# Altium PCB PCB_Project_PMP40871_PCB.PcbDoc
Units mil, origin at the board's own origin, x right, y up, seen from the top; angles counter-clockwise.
Board outline 2300 x 1200 mil, 2 copper layers (Top Layer, Bottom Layer), stack 35.6 mil thick; 25 components, 9 nets, 72 pads, 26 vias.
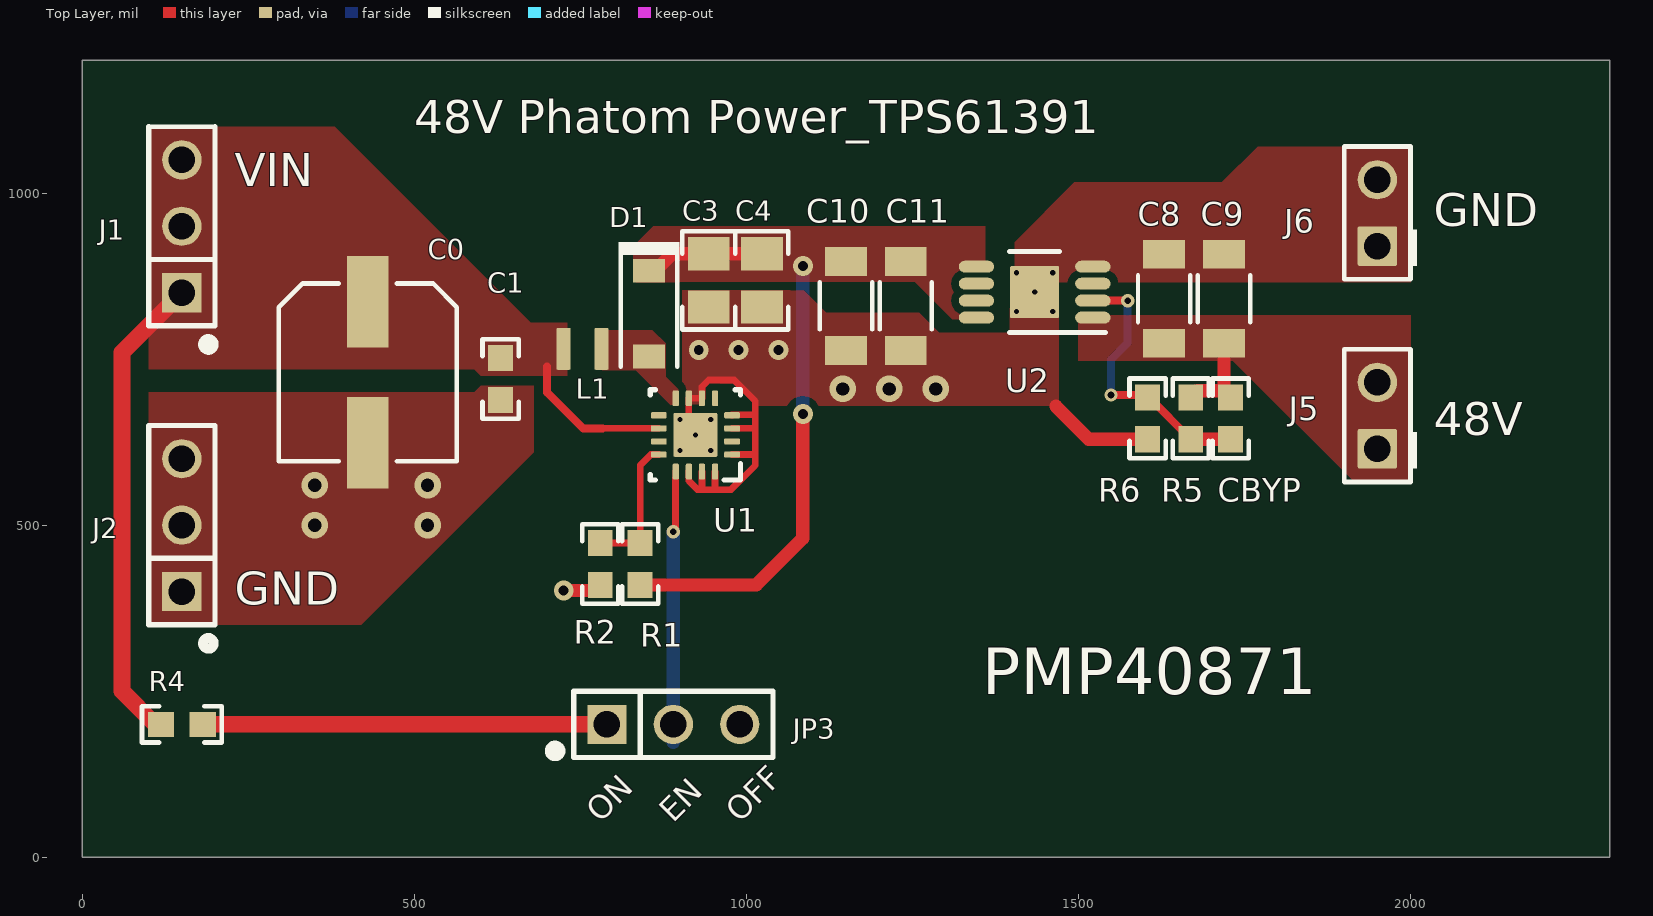
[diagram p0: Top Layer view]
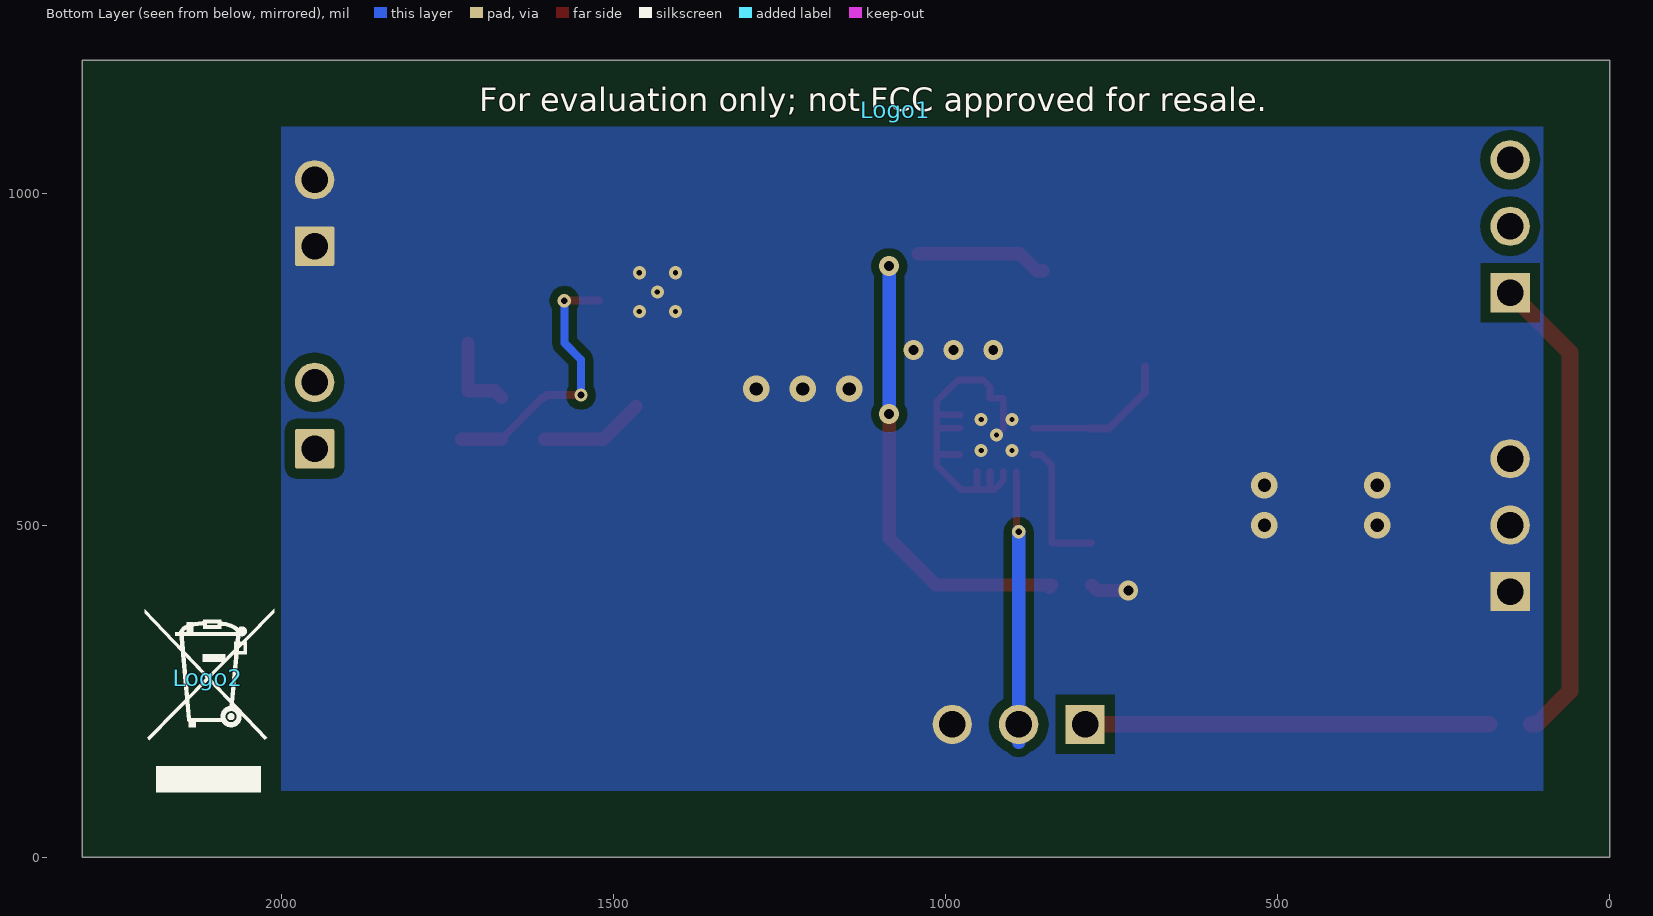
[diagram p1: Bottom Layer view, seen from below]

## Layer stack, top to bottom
Top Solder: solder mask 0.4, Solder Resist, Dk 3.5
Top Layer: signal copper 2.8
Dielectric1: core 30, Dk 4.2
Bottom Layer: signal copper 2.8
Bottom Solder: solder mask 0.4, Solder Resist, Dk 3.5

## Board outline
0,0 2300,0 2300,1200 0,1200

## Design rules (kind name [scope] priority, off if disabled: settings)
AcuteAngle [All] p1: minimum=4.50000000000000E+0001 checktracksonly=FALSE
AssemblyTestPointUsage [All] p1: valid=2
Clearance Clearance_BoardEdge_MountingHoles [OnCopper and InComponentClass('Mounting Holes') vs IsKeepOut] p1: gap=40 ignorepadtopadclearanceinfootprint=FALSE except(0: Arc-Hole Track-Hole SMDPad-Hole THPad-Hole Via-Hole Fill-Hole Poly-Hole Region-Hole Text-Hole)
Clearance Clearance_BoardEdge_Poly [OnCopper and InPoly vs IsKeepOut] p2: gap=25 ignorepadtopadclearanceinfootprint=FALSE except(0: Arc-Hole Track-Hole SMDPad-Hole THPad-Hole Via-Hole Fill-Hole Poly-Hole Region-Hole Text-Hole)
Clearance Clearance_BoardEdge [OnCopper and Not InComponentClass('Logo') and not InComponentClass('FiducialMark') and not InRegion(1000,500,4000,800) and Not IsKeepout vs IsKeepOut] p3: gap=5 ignorepadtopadclearanceinfootprint=FALSE except(0: Arc-Hole Track-Hole SMDPad-Hole THPad-Hole Via-Hole Fill-Hole Poly-Hole Region-Hole Text-Hole)
Clearance Clearance_Poly [InPolygon] p4: gap=10 ignorepadtopadclearanceinfootprint=FALSE except(0: Arc-Hole Track-Hole SMDPad-Hole THPad-Hole Via-Hole Fill-Hole Poly-Hole Region-Hole Text-Hole)
Clearance [All] p5: gap=7.5 ignorepadtopadclearanceinfootprint=FALSE
ComponentClearance ComponentClearance_Logo [All] p1: gap=10 collisioncheckmode=3 verticalgap=10 showdistances=TRUE
ComponentClearance ComponentClearance_ScrewToNut [(HasFootprint('NY PMS 440 0025 PH')) vs (HasFootprint('Keystone_1902C'))] p2: gap=5 collisioncheckmode=3 verticalgap=10 showdistances=FALSE
ComponentClearance ComponentClearance_MountingHoles [InComponentClass('Mounting Holes')] p3: gap=10 collisioncheckmode=3 verticalgap=100000 showdistances=FALSE
ComponentClearance ComponentClearance_SmallPassives [HasFootprint('0201*') or HasFootprint('0402*') or HasFootprint('0508') or HasFootprint('0603*') or HasFootprint('0612') or HasFootprint('0805*') or HasFootprint('0815*') or HasFootprint('0830*') or HasFootprint('1206*') or HasFootprint('1210*') or HasFootprint('1808*') or HasFootprint('1812*') or HasFootprint('1825*') or HasFootprint('2010*') or HasFootprint('2220*') or HasFootprint('2225*') or HasFootprint('2512*') or HasFootprint('2728*') or HasFootprint('3518*') vs HasFootprint('0201*') or HasFootprint('0402*') or HasFootprint('0508') or HasFootprint('0603*') or HasFootprint('0612') or HasFootprint('0805*') or HasFootprint('0815*') or HasFootprint('0830*') or HasFootprint('1206*') or HasFootprint('1210*') or HasFootprint('1808*') or HasFootprint('1812*') or HasFootprint('1825*') or HasFootprint('2010*') or HasFootprint('2220*') or HasFootprint('2225*') or HasFootprint('2512*') or HasFootprint('2728*') or HasFootprint('3518*')] p4: gap=10 collisioncheckmode=3 verticalgap=10 showdistances=FALSE
ComponentClearance ComponentClearance_THtoSMT [IsThruComponent vs IsSMTComponent] p5: gap=10 collisioncheckmode=3 verticalgap=100000 showdistances=FALSE
ComponentClearance ComponentClearance_THtoTH [IsThruComponent vs IsThruComponent] p6: gap=10 collisioncheckmode=3 verticalgap=100000 showdistances=FALSE
ComponentClearance [All] p7: gap=10 collisioncheckmode=3 verticalgap=10 showdistances=FALSE
DiffPairsRouting [All] p1: maxlimit=100 minlimit=10 mostfreqgap=10 toplayer_minwidth=15 toplayer_maxwidth=15 toplayer_prefwidth=15 bottomlayer_minwidth=15 bottomlayer_maxwidth=15 bottomlayer_prefwidth=15 maxuncoupledlength=1000
FabricationTestPointUsage TestPointUsage [All] p1: valid=2 allowmultiple=FALSE
FabricationTestpoint Testpoint [All] p1: side=3 testpointundercomponent=TRUE minsize=40 maxsize=100 preferedsize=60 minholesize=0 maxholesize=40 preferedholesize=32 testpointgrid=1 allowsidetop=TRUE allowsidebottom=TRUE usegrid=TRUE gridtolerance=0.01
FanoutControl Fanout_LCC [IsLCC] p1: bgadir=Out bgaviamode=Centered fanoutstyle=Auto fanoutdirection=Alternating viagrid=1 // Fanout_LCC (Default Rule)
FanoutControl Fanout_BGA [IsBGA] p2: bgadir=Out bgaviamode=Centered fanoutstyle=Auto fanoutdirection=Alternating viagrid=1 // Fanout_BGA (Default Rule)
FanoutControl Fanout_Default [All] p4: bgadir=Out bgaviamode=Centered fanoutstyle=Auto fanoutdirection=Alternating viagrid=1 // Fanout_Default (Default Rule)
FanoutControl Fanout_Small [(CompPinCount < 5)] p5: bgadir=Out bgaviamode=Centered fanoutstyle=Auto fanoutdirection=OutThenIn viagrid=1 // Fanout_Small (Default Rule)
HoleSize [All] p1: absolutevalues=TRUE maxlimit=251 minlimit=6 maxpercent=80.000 minpercent=20.000
MinimumAnnularRing [All] p1: minimumring=3
MinimumSolderMaskSliver MinimumSolderMaskSliver_Logo [InComponentClass('Logo') vs InComponentClass('Logo')] p1: minsoldermaskwidth=0.7
MinimumSolderMaskSliver [All] p2: minsoldermaskwidth=0
PlaneConnect [All] p1: planeconnectstyle=Direct reliefexpansion=10 reliefentries=4 reliefconductorwidth=10 reliefairgap=10
PolygonConnect [All] p1: connectstyle=Direct reliefconductorwidth=10 reliefentries=4 polygonreliefangle="90 Angle" airgapwidth=10
RoutingCorners [All] p1: cornerstyle=45-Degree minsetback=10 maxsetback=100
RoutingVias [All] p1: holewidth=16 width=34 viastyle="Through Hole" minholewidth=7 minwidth=16 maxholewidth=40 maxwidth=65
SMDToCorner [All] p1: distance=0
SilkToBoardRegionClearance [Not ((IsComment or IsDesignator) And (Hide <> 'False')) and not InRegion(1000,500,4000,800)] p1:
SilkToSilkClearance [All] p1: silktosilkclearance=0
SilkToSolderMaskClearance SilkscreenOverComponentPads [IsPad] p1: minsilkscreentomaskgap=0 clearancetoexposedcopper=TRUE
SolderMaskExpansion [All] p1: expansion=3
Width [All] p1: maxlimit=100 minlimit=6 preferedwidth=10 checkconnectedcopper=TRUE
14 further rules are at their usual default settings.

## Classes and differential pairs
component class Header: J1 J2 J5 J6 J7 J9 JP3

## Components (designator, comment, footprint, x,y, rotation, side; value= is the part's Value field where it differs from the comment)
C0 "EEHZA1E101XP" SM_RADIAL_6.3BMM 430,730 r270 top value=100uF
C1 "GRM188R61C475KAAJ" 0603 630,720 r270 top value=4.7uF
C3 "C2012X7S2A474K125AB" 0805_HV 943.29,868.52 r270 top value=0.47uF
C4 "C2012X7S2A474K125AB" 0805_HV 1023.29,868.52 r270 top value=0.47uF
C8 "CGA5L1X7R1H106K160AC" 1206_190 1629.02,840.87 r90 top value=10uF
C9 "CGA5L1X7R1H106K160AC" 1206_190 1719.02,840.87 r90 top value=10uF
C10 "CGA5L3X7S2A225K160AB" 1206_180 1150,830 r270 top value=2.2uF
C11 "CGA5L3X7S2A225K160AB" 1206_180 1240,830 r270 top value=2.2uF
CBYP "C0603C103J1RACTU" 0603 1729.02,660.87 r270 top value=0.01uF
D1 "BAS16D-E3-08" SOD-123 853.29,818.52 r270 top value=100V
J1 "Header_3x1_Launchpad" CONN_PEC03SAAN 150,950 r90 top
J2 "Header_3x1_Launchpad" CONN_PEC03SAAN 150,500 r90 top
J5 "Header_2x1" CONN_PEC02SAAN 1950,665 r90 top
J6 "Header_2x1" CONN_PEC02SAAN 1950,970 r90 top
JP3 "Header_3x1_Launchpad" CONN_PEC03SAAN 890,200 r0 top
L1 "DFE201612E-4R7M=P2" DFE201612E 753.29,765.41 r0 top value=4.7uH
Logo1 "FCC disclaimer" FCC_disclaimer 1075,1125 r180 bottom
Logo2 "WEEE logo" WEEE_Minimum 2110,270 r180 bottom
R1 "RT0603BRD07392KL" 0603 840,441.5 r270 top value=392k
R2 "Resistor" 0603 780,441.5 r90 top value=10.0k
R4 "Resistor" 0603 150,200 r180 top value=10.0k
R5 "RC0603FR-07475KL" 0603 1669.02,660.87 r90 top value=475k
R6 "RC0603FR-0712KL" 0603 1604.02,660.87 r90 top value=12.0k
U1 "TPS61391RGT" RGT0016C 923.29,635.78 r180 top
U2 "TPS7A4101DGNR" DGN0008B_N 1434.02,850.87 r180 top

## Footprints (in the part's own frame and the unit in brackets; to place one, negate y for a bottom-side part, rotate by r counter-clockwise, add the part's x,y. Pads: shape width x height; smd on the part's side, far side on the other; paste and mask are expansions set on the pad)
0603 [mm] "0603 from SM-752 data"
  rect 1x0.95 smd: 1(-0.8,0) 2(0.8,0)
  silkscreen extent -1.52,-0.69 1.52,0.69, body extent -0.87,-0.47 0.87,0.47, height 1
0805_HV [mil] "0805 with 30mil clearance between pads"
  rect 50x63 smd: 1(-40,0) 2(40,0)
  silkscreen extent -74,-40 74,40, body extent -43,-29 43,29, height 57
1206_180 [mm] "1206_180"
  rect 1.1x1.6 smd: 1(-1.7,0) 2(1.7,0)
  silkscreen extent -0.9,-1 0.9,1, body extent -1.75,-0.95 1.75,0.95, height 1.8
1206_190 [mm] "1206_190"
  rect 1.1x1.6 smd: 1(-1.7,0) 2(1.7,0)
  silkscreen extent -0.9,-1 0.9,1, body extent -1.75,-0.95 1.75,0.95, height 1.9
CONN_PEC02SAAN [mm] "SULLINS"
  rrect7% 1.5x1.5 hole 1.016: 1(-1.27,0)
  round 1.5 hole 1.016: 2(1.27,0)
  silkscreen extent -2.54,-1.52 2.54,1.27, body extent -2.54,-1.27 2.54,1.27, height 8.38
CONN_PEC03SAAN [mm] "SULLINS"
  rect 1.5x1.5 hole 1.016: 1(-2.54,0)
  round 1.5 hole 1.016: 2(0,0) 3(2.54,0)
  silkscreen extent -4.72,-1.27 3.81,1.27, body extent -3.84,-1.3 3.84,1.3, height 8.38
DFE201612E [mm] "MuRata recommended"
  rrect18% 0.55x1.6 smd: 1(-0.725,0) 2(0.725,0)
  body extent -1.1,-0.9 1.1,0.9, height 1.2
DGN0008B_N [mm] "TSOP, 8-Leads, Body 3x3mm, Pitch 0.65mm, Thermal Pad 1.92x1.60mm, IPC Medium Density"
  rrect100% 1.35x0.45 smd: 1(-2.225,0.975) 2(-2.225,0.325) 3(-2.225,-0.325) 4(-2.225,-0.975) 5(2.225,-0.975) 6(2.225,-0.325) 7(2.225,0.325) 8(2.225,0.975)
  rrect5% 1.88x1.98 smd: 9(0,0)
  silkscreen extent -2.7,-1.55 0.95,1.55, body extent -2.46,-1.5 2.46,1.5, height 1.1
FCC_disclaimer [mil]
RGT0016C [mm] "QFN, 16-Leads, Body 3x3mm, Pitch 0.5mm, Thermal Pad 1.7x1.7mm, TI Recommended"
  rrect42% 0.6x0.24 smd: 1(-1.4,0.75) 2(-1.4,0.25) 3(-1.4,-0.25) 4(-1.4,-0.75) 9(1.4,-0.75) 10(1.4,-0.25) 11(1.4,0.25) 12(1.4,0.75)
  rrect42% 0.24x0.6 smd: 5(-0.75,-1.4) 6(-0.25,-1.4) 7(0.25,-1.4) 8(0.75,-1.4) 13(0.75,1.4) 14(0.25,1.4) 15(-0.25,1.4) 16(-0.75,1.4)
  rrect6% 1.55x1.55 on Top Paste: 17(0,0)
  rrect6% 1.68x1.68 smd paste-0.85: 17(0,0)
  silkscreen extent -1.72,-1.72 1.73,1.73, body extent -1.5,-1.5 1.5,1.5, height 1
SM_RADIAL_6.3BMM [mm] "Nichicon 6.3x7.7"
  rect 3.5x1.6 smd: 1(-2.7,0) 2(2.7,0)
  silkscreen extent -3.4,-3.4 3.4,3.4, body extent -3.4,-3.4 3.4,3.4, height 8
SOD-123 [mm] "On Semi recommended land pattern"
  rect 0.915x1.22 smd: 1(-1.637,0) 2(1.637,0)
  silkscreen extent -2.74,-1.17 2.03,1.17, body extent -1.93,-0.9 1.93,0.9, height 1.35
WEEE_Minimum [mil] "WEEElie bin"
  silkscreen extent -95,-172 99,104

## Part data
C0: library part CMP-0012570-3, "CAP, Polymer Hybrid, 100 uF, 25 V, +/- 20%, 30 ohm, 6.3x7.7 SMD", Manufacturer=Panasonic, Supplier Part Number 1=P15436CT-ND, Tolerance_%=20%, Value1="30 ohm", Value2=25V, ValueDisplayed=100uF
C1: library part CMP-0007341-5, "CAP, CERM, 4.7 uF, 16 V, +/- 10%, X5R, 0603", Cap_Case=0603, Manufacturer=MuRata, Supplier Part Number 1=490-10481-1-ND, TempCo=X5R, Tolerance_%=10%, Value1=Unknown, Value2=16V, ValueDisplayed=4.7uF
C3 C4: "CAP, CERM, 0.47 µF, 100 V,+/- 10%, X7S, 0805", Cap_Case=0805, Manufacturer=TDK, Supplier Part Number 1=445-5203-1-ND, TempCo=X7S, Tolerance_%=10, Value1="0.017152 ohm", Value2=100V, ValueDisplayed=0.47µF
C8 C9: library part CMP-0085950-1, "CAP, CERM, 10 µF, 50 V,+/- 10%, X7R, AEC-Q200 Grade 1, 1206", Cap_Case=1206, Manufacturer=TDK, TempCo=X7R, Tolerance_%=10%, Value2=50V, ValueDisplayed=10µF
C10 C11: "CAP, CERM, 2.2 µF, 100 V,+/- 10%, X7S, AEC-Q200 Grade 1, 1206", Cap_Case=1206, Manufacturer=TDK, Supplier Part Number 1=445-6994-1-ND, TempCo=X7S, Tolerance_%=10, Value1="0.005718 ohm", Value2=100V, ValueDisplayed=2.2µF
CBYP: "CAP, CERM, 0.01 µF, 100 V,+/- 5%, X7R, 0603", Cap_Case=0603, Manufacturer=Kemet, Supplier Part Number 1=399-3190-1-ND, TempCo=X7R, Tolerance_%=5, Value2=100V, ValueDisplayed=0.01µF
D1: library part CMP-0080761-1, "Diode, Switching, 100 V, 0.25 A, AEC-Q101, SOD-123", Manufacturer=Vishay-Semiconductor, Supplier Part Number 1=BAS16D-E3-08GICT-ND, Value1=0.25A, Value2=1.25V
J1 J2 JP3: library part CMP-0002338-1, "Header, 100mil, 3x1, Tin, TH", Color=Black, Current_A=3A, Manufacturer="Sullins Connector Solutions", PartNumber=PEC03SAAN, Supplier Part Number 1=S1012E-03-ND, Voltage_V=1.8kV
J5 J6: library part CMP-0002337-1, "Header, 100mil, 2x1, Tin, TH", Color=Black, Current_A=3A, Manufacturer="Sullins Connector Solutions", PartNumber=PEC02SAAN, Supplier Part Number 1=S1012E-02-ND, Voltage_V=1.8kV
L1: library part CMP-0080776-1, "Inductor, Shielded, Metal Composite, 4.7 µH, 1.2 A, 0.252 ohm, SMD", Manufacturer=MuRata, PartNumber=DFE201612E-4R7M{}P2, Value1="0.252 ohm", Value2=1.2A, ValueDisplayed=4.7µH
Logo1: library part CMP-0074847-1, "FCC_disclaimer"
Logo2: library part CMP-0074769-1
R1: "RES, 392 k, 0.1%, 0.1 W, 0603", Manufacturer="Yageo America", Power_W=0.1, TempCo="25 ppm/C", Value1=0.1%, Value2=0.1W, Value_Code=392k
R2 R4: library part CMP-0021998-4, "RES, 10.0 k, 1%, 0.1 W, AEC-Q200 Grade 0, 0603", Manufacturer=Vishay-Dale, PartNumber=CRCW060310K0FKEA, Power_W=100mW, Supplier Part Number 1=541-10.0KHCT-ND, TempCo="100 ppm/C", Tolerance_%=1%, Value2=0.1W, Value_Code=10k0, ValueDisplayed=10.0k
R5: library part CMP-0023130-4, "RES, 475 k, 1%, 0.1 W, 0603", Manufacturer=Yageo, Power_W=100mW, Supplier Part Number 1=311-475KHRCT-ND, TempCo="100 ppm/C", Tolerance_%=1%, Value2=0.1W, Value_Code=475k
R6: library part CMP-0022779-5, "RES, 12.0 k, 1%, 0.1 W, 0603", Manufacturer=Yageo, Power_W=100mW, Supplier Part Number 1=311-12.0KHRCT-ND, TempCo="100 ppm/C", Tolerance_%=1%, Value2=0.1W, Value_Code=12k0, ValueDisplayed=12.0k
U1: library part CMP-0860736-1, "85-VOUT Boost Converter with Current Mirror and Sample / Hold, RGT0016C (VQFN-16)", Alternate Manufacturer="Texas Instruments"
U2: "Single Output LDO, 50 mA, Adjustable 1.175 to 48 V Output, 7 to 50 V Input, 8-pin MSOP (DGN), -40 to 125 degC, Green (RoHS & no Sb/Br)", Alternate Manufacturer="Texas Instruments", Alternate PartNumber=Equivalent, Supplier Part Number 1=296-30081-2-ND

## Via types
v1: diameter 19.68, hole 7.87, Top Layer to Bottom Layer, 10 vias
v2: diameter 40, hole 20, Top Layer to Bottom Layer, 7 vias
v3: diameter 30, hole 15, Top Layer to Bottom Layer, 6 vias
v4: diameter 20, hole 10, Top Layer to Bottom Layer, 3 vias

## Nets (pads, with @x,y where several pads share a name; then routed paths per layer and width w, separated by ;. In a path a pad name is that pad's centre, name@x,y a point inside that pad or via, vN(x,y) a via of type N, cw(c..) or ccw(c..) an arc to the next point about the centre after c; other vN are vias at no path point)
EN: JP3.2 U1.13 | length 409.4
  Top Layer w10: v4(890,490) 893.29,493.29 893.29,570.78 893.76,571.25 U1.13
  Bottom Layer w20: JP3.2@890,172.79 v4(890,490)
FB: R1.1 R2.2 U1.12 | length 211.9
  Top Layer w10: R2.2 R1.1 840,590 856.25,606.25 U1.12
FB1: CBYP.2 R5.1 R6.2 U2.2 | length 405.1
  Top Layer w12: U2.2 v4@1566.81,838.07 ; v4(1549.02,695.87) 1600.51,695.87 R6.2 1606.02,692.36 R5.1
  Top Layer w20: R5.1 CBYP.2
  Bottom Layer w12: v4(1549.02,695.87) 1549.02,749.02 1574.02,774.02 v4(1574.02,837.87)
GND: C0.2 C1.2 C3.2 C4.2 C8.2 C9.2 C10.2 C11.2 J2.1 J2.2 J2.3 J6.1 J6.2 JP3.3 R2.1 R6.1 U1.1 U1.3 U1.4 U1.6 U1.7 U1.14 U1.15 U1.16 U1.17@923.29,635.78 U2.4 U2.9 | length 797.9
  Top Layer w10: U1.14 913.44,566.56 926.48,553.52 976.85,553.52 1013.29,589.95 1013.29,686.71 981.48,718.52 943.29,718.52 933.13,708.36 U1.6 U1.7 913.44,645.62 v1(923.29,635.78) ; 933.13,553.67 U1.15 ; 952.81,553.99 U1.16 ; U1.1 1009.74,606.25 1010,606.52 ; U1.3 1013.29,645.62 ; U1.4 978.4,666 1013.29,666
  Top Layer w20: v3(725,401.5) 771.5,401.5 R2.1 ; 1466.07,678.93 1515.63,629.37 R6.1
  other v1: 900.06,612.55 946.52,612.55 900.06,659.01 946.52,659.01 1406.85,821.73 1461.18,821.73 1434.02,850.87 1406.85,880 1461.18,880
  other v2: 350,500 520,500 350,560 520,560 1145,705 1215,705 1285,705
  other v3: 928.29,763.52 988.29,763.52 1048.29,763.52
NetJP3_1: JP3.1 R4.1 | length 608.5
  Top Layer w25: R4.1 JP3.1
SW: D1.2 L1.2 U1.8
VIN: C0.1 C1.1 J1.1 J1.2 J1.3 L1.1 R4.2 U1.10 | length 945.7
  Top Layer w10: 783.29,645.62 U1.10
  Top Layer w12: 700,738.52 700,700 754.38,645.62 783.29,645.62
  Top Layer w25: R4.2 110,200 60,250 60,760 J1.1
VOUT: C8.1 C9.1 CBYP.1 J5.1 J5.2 R5.2 U2.1 | length 125.7
  Top Layer w20: R5.2 1679.02,702.36 1719.02,702.36 C9.1
Vout1: C3.1 C4.1 C10.1 C11.1 D1.1 R1.2 U2.5 U2.8 | length 887.7
  Top Layer w20: R1.2@843.5,406.5 R1.2 1015,410 1085,480 v3(1085,667.23) ; D1.1 862.98,882.98 888.52,908.52 C3.1 C4.1 C4.1@1041.48,908.52
  Bottom Layer w20: v3(1085,667.23) v3(1085,890)
pads on no net: U1.2 U1.5 U1.9 U1.11 U1.17@923.29,635.78 U2.3 U2.6 U2.7
copper on no net: | length 60632.3
  Top Layer w1: 6346.64,537.82 6446.33,637.5 6566.33,757.5 6686.33,877.5 6806.33,997.5 6926.33,1117.5 7046.33,1237.5 ; 6346.64,597.82 6386.33,637.5 6506.33,757.5 6626.33,877.5 6746.33,997.5 6866.33,1117.5 6986.33,1237.5 ; 6346.64,657.82 6446.33,757.5 6566.33,877.5 6686.33,997.5 6806.33,1117.5 6926.33,1237.5 ; 6346.64,717.82 6386.33,757.5 6506.33,877.5 6626.33,997.5 6746.33,1117.5 6866.33,1237.5 ; 6346.64,777.82 6446.33,877.5 6566.33,997.5 6686.33,1117.5 6806.33,1237.5 ; 6346.64,837.82 6386.33,877.5 6506.33,997.5 6626.33,1117.5 6746.33,1237.5 ; 6346.64,897.82 6446.33,997.5 6566.33,1117.5 6686.33,1237.5 ; 6346.64,957.82 6386.33,997.5 6506.33,1117.5 6626.33,1237.5 ; 6346.64,1017.82 6446.33,1117.5 6566.33,1237.5 ; 6346.64,1077.82 6386.33,1117.5 6506.33,1237.5 ; 6346.64,1137.82 6446.33,1237.5 ; 6346.64,1197.82 6386.33,1237.5 ; 6386.33,517.5 6506.33,637.5 6626.33,757.5 6746.33,877.5 6866.33,997.5 6986.33,1117.5 7106.33,1237.5 ; 6446.33,517.5 6566.33,637.5 6686.33,757.5 6806.33,877.5 6926.33,997.5 7046.33,1117.5 7166.33,1237.5 ; 6506.33,517.5 6626.33,637.5 6746.33,757.5 6866.33,877.5 6986.33,997.5 7106.33,1117.5 7226.33,1237.5 ; 6566.33,517.5 6686.33,637.5 6806.33,757.5 6926.33,877.5 7046.33,997.5 7166.33,1117.5 7286.33,1237.5 ; 6626.33,517.5 6746.33,637.5 6866.33,757.5 6986.33,877.5 7106.33,997.5 7226.33,1117.5 7346.33,1237.5 ; 6686.33,517.5 6806.33,637.5 6926.33,757.5 7046.33,877.5 7166.33,997.5 7286.33,1117.5 7406.33,1237.5 ; 6746.33,517.5 6866.33,637.5 6986.33,757.5 7106.33,877.5 7226.33,997.5 7346.33,1117.5 7466.33,1237.5 ; 6806.33,517.5 6926.33,637.5 7046.33,757.5 7166.33,877.5 7286.33,997.5 7406.33,1117.5 7466.33,1177.5 ; 6866.33,517.5 6986.33,637.5 7106.33,757.5 7226.33,877.5 7346.33,997.5 7466.33,1117.5 ; 6926.33,517.5 7046.33,637.5 7166.33,757.5 7286.33,877.5 7406.33,997.5 7466.33,1057.5 ; 6986.33,517.5 7106.33,637.5 7226.33,757.5 7346.33,877.5 7466.33,997.5 ; 7046.33,517.5 7166.33,637.5 7286.33,757.5 7406.33,877.5 7466.33,937.5 ; 7106.33,517.5 7226.33,637.5 7346.33,757.5 7466.33,877.5 ; 7166.33,517.5 7286.33,637.5 7406.33,757.5 7466.33,817.5 ; 7226.33,517.5 7346.33,637.5 7466.33,757.5 ; 7286.33,517.5 7406.33,637.5 7466.33,697.5 ; 7346.33,517.5 7466.33,637.5 ; 7406.33,517.5 7466.33,577.5
  Top Layer w15: 2997.5,637.5 3407.41,637.5 4267.18,637.5 5126.95,637.5 5776.78,637.5 6346.64,637.5 7466.33,637.5 ; 2997.5,757.5 3407.41,757.5 4267.18,757.5 5126.95,757.5 5776.78,757.5 6346.64,757.5 7466.33,757.5 ; 2997.5,877.5 3407.41,877.5 4267.18,877.5 5126.95,877.5 5776.78,877.5 6346.64,877.5 7466.33,877.5 ; 2997.5,997.5 3407.41,997.5 4267.18,997.5 5126.95,997.5 5776.78,997.5 6346.64,997.5 7466.33,997.5 ; 2997.5,1117.5 3407.41,1117.5 4267.18,1117.5 5126.95,1117.5 5776.78,1117.5 6346.64,1117.5 7466.33,1117.5 ; 2997.5,1237.5 7466.33,1237.5 ; 3407.41,1357.5 3407.41,517.5 ; 4267.18,1357.5 4267.18,517.5 ; 5126.95,1357.5 5126.95,517.5 ; 5776.78,1357.5 5776.78,517.5 ; 6346.64,1357.5 6346.64,517.5 ; 3407.41,517.5 4267.18,517.5 ; 3407.41,517.5 2997.5,517.5 2997.5,1357.5 7466.33,1357.5 7466.33,517.5 6346.64,517.5 ; 4267.18,517.5 5126.95,517.5 ; 5126.95,517.5 5776.78,517.5 ; 5776.78,517.5 6346.64,517.5

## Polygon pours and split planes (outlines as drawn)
GND on Top Layer "Top Layer-No Net 1" (solid, pour order 90): 903.29,853.52 1086.48,853.52 1120,820 1260,820 1290.16,789.84 1396.61,789.84 1396.61,826.61 1410,840 1470,840 1470,680 1013.29,680 1013.29,681.61 981,713.9 943.99,713.9 938,707.91 938,684 936,682 909,682 909,710.11 903.29,715.82
Vout1 on Top Layer "Top Layer-No Net" (solid, pour order 88): 830,920 860,950 1360,950 1360,810 1310,810 1254.57,865.43 834.57,865.43 830,870
SW on Top Layer "TOP_LAYER_SW_P016" (solid, remove dead copper, pour order 16): 783.29,793.52 858.29,793.52 878.29,773.52 878.29,723.52 898.29,703.52 898.29,678.52 888.29,678.52 833.29,733.52 783.29,733.52
GND on Top Layer "TOP_LAYER_GND_P006" (solid, remove dead copper, pour order 6): 100,350 420,350 680,610 680,710 600,710 590,700 100,700
VIN on Top Layer "TOP_LAYER_VIN_P004" (solid, remove dead copper, pour order 4): 100,1100 380,1100 675,805 730,805 730,725 600,725 590,735 100,735
GND on Top Layer "Top Layer-No Net 2" (solid, remove dead copper, pour order 68): 1404.02,925.87 1494.02,1015.87 1715.87,1015.87 1770.02,1070.02 2000,1069.99 2000,865.88 1404.02,865.87
VOUT on Top Layer "Top Layer-No Net 3" (solid, remove dead copper, pour order 70): 2000,815.87 2000,565.87 1914.13,565.87 1732.38,747.62 1500,747.62 1500,810 1505.87,815.87
GND on Bottom Layer "Bottom Layer-No Net" (solid, remove dead copper, pour order 62): 100,1100 2000,1100 2000,100 100,100

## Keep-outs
Keep-Out Layer:
  text ".Layer_Name" at 577,-858.49 h60

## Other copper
Top Layer:
  text "Layer" at 3057.5,1267.5 h60
  text "Name" at 3467.41,1267.5 h60
  text "Material" at 4327.18,1267.5 h60
  text "Thickness" at 5186.95,1267.5 h60
  text "Constant" at 5836.78,1267.5 h60
  text "Board Layer Stack" at 6406.64,1267.5 h60
  text "1" at 3057.5,1147.5 h60
  text "Top Overlay" at 3467.41,1147.5 h60
  text "2" at 3057.5,1027.5 h60
  text "Top Solder" at 3467.41,1027.5 h60
  text "Solder Resist" at 4327.18,1027.5 h60
  text "0.40mil" at 5186.95,1027.5 h60
  text "3.5" at 5836.78,1027.5 h60
  text "3" at 3057.5,907.5 h60
  text "Top Layer" at 3467.41,907.5 h60
  text "Copper" at 4327.18,907.5 h60
  text "2.80mil" at 5186.95,907.5 h60
  text "4" at 3057.5,787.5 h60
  text "Dielectric1" at 3467.41,787.5 h60
  text "30.00mil" at 5186.95,787.5 h60
  text "4.2" at 5836.78,787.5 h60
  text "5" at 3057.5,667.5 h60
  text "Bottom Layer" at 3467.41,667.5 h60
  text "Copper" at 4327.18,667.5 h60
  text "2.80mil" at 5186.95,667.5 h60
  text "6" at 3057.5,547.5 h60
  text "Bottom Solder" at 3467.41,547.5 h60
  text "Solder Resist" at 4327.18,547.5 h60
  text "0.40mil" at 5186.95,547.5 h60
  text "3.5" at 5836.78,547.5 h60
  text ".Layer_Name" at 577,-858.49 h60
Bottom Layer:
  text ".Layer_Name" at 577,-858.49 h60

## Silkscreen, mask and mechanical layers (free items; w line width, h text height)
Top Overlay:
  text "48V Phatom Power_TPS61391" at 500,1090 h50
  text "VIN" at 230,1010 h50
  text "GND" at 2035,950 h50
  text "48V" at 2035,635 h50
  text "GND" at 230,380 h50
  text "PMP40871" at 1355,245 h70
  text "ON" at 780,50 h35 r45
  text "EN" at 890,50 h35 r45
  text "OFF" at 990,50 h35 r45
  text ".Layer_Name" at 577,-858.49 h60
Bottom Overlay:
  text ".Layer_Name" at 577,-858.49 h60
Top Paste:
  text ".Layer_Name" at 577,-858.49 h60
Bottom Paste:
  text ".Layer_Name" at 577,-858.49 h60
Top Solder:
  text ".Layer_Name" at 577,-858.49 h60
  text ".Layer_Name" at 577,-858.49 h60
Bottom Solder:
  text ".Layer_Name" at 577,-858.49 h60
Drill Guide:
  text ".Layer_Name" at 577,-858.49 h60
M1 Board Outline:
  lines w10: 0,0 2300,0 ; 0,0 0,1200 ; 0,0 2300,0 ; 0,0 0,1200 ; 0,1200 2300,1200 ; 0,1200 2300,1200 ; 2300,0 2300,1200 ; 2300,0 2300,1200
  text ".Layer_Name" at 577,-858.49 h60
M2 Board Dimensions:
  rectangle: 0,-275 125,-150
  rectangle: 125,-400 500,-275
  lines w7: 0,-275 1000,-275 ; 125,-400 125,-150 ; 250,-400 250,-150 ; 500,-400 500,-150 ; 750,-400 750,-150 ; 0,-400 1000,-400 1000,-150 0,-150 0,-400
  text ".Layer_Name" at 577,-858.49 h60
M3 3D STEP Top:
  text ".Layer_Name" at 577,-858.49 h60
M4 3D STEP Bottom:
  text ".Layer_Name" at 577,-858.49 h60
M5 Assembly Top:
  lines w10: -292,-930.17 6308,-930.17 ; -292,-726.83 6310,-726.83 ; -292,-523.5 -292,-1133.5 3713,-1133.5 6310,-1133.5 6310,-523.5 -291.5,-523.5 -291.5,-1133.5 1284,-1133.5 ; 2173,-1133.5 2173,-523.5 ; 3440,-726.83 3440,-523.5 ; 4280,-726.83 4280,-523.5 ; 4902,-1140 4902,-937.17
  text "COMPONENTS MARKED 'DNP' SHOULD NOT BE POPULATED." at 1153.5,-318.5 h35
  text "ASSEMBLY VARIANT:" at 1153,-434 h35
  text ".VariantName" at 2189,-434 h35
  text "PCB VIEWED FROM TOP SIDE" at -228.5,-655.67 h60
  text "BOARD #:" at 2248,-655.67 h60
  text ".PRJ_Number" at 2793.5,-655.67 h60
  text "REV:" at 3638,-655.67 h60
  text ".PCB_Rev" at 3929.5,-655.67 h60
  text "SVN REV:" at 4476,-655.67 h60
  text ".VersionControl_RevNumber" at 4982,-655.67 h60
  text "TID #:" at 2248,-859 h60
  text ".TID" at 2793.5,-859 h60
  text "PLOT NAME =" at -228.5,-1064.34 h60
  text ".plot_File_Name" at 577,-1064.34 h60
  text "GENERATED    :" at 2250,-1064.34 h60
  text ".Print_Date" at 3119.5,-1064.34 h60
  text ".Print_Time" at 3848.5,-1064.34 h60
  text "TEXAS INSTRUMENTS" at 5113,-1064.34 h60
M6 Assembly Bottom:
  lines w10: -292.5,-727.33 6309.5,-727.33 ; -290.5,-930.67 6309.5,-930.67 ; 1115.5,-1140.5 1115.5,-937.67 ; 1737.5,-727.33 1737.5,-524 ; 2577.5,-727.33 2577.5,-524 ; 3844.5,-1134 3844.5,-524 ; 4733.5,-1134 6309,-1134 6309,-524 -292.5,-524 -292.5,-1134 2304.5,-1134 6309.5,-1134 6309.5,-524
  text "COMPONENTS MARKED 'DNP' SHOULD NOT BE POPULATED." at 6102,-318 h35
  text ".VariantName" at 5058,-434 h35
  text "ASSEMBLY VARIANT:" at 6097,-434 h35
  text ".VersionControl_RevNumber" at 1035.5,-656.17 h60
  text "SVN REV:" at 1541.5,-656.17 h60
  text ".PCB_Rev" at 2088,-656.17 h60
  text "REV:" at 2379.5,-656.17 h60
  text ".PRJ_Number" at 3224,-656.17 h60
  text "BOARD #:" at 3769.5,-656.17 h60
  text "PCB VIEWED FROM BOTTOM SIDE" at 6246,-656.17 h60
  text ".TID" at 3224,-859.5 h60
  text "TID #:" at 3769.5,-859.5 h60
  text "TEXAS INSTRUMENTS" at 904.5,-1064.84 h60
  text ".Print_Time" at 2169,-1064.84 h60
  text ".Print_Date" at 2898,-1064.84 h60
  text "GENERATED    :" at 3767.5,-1064.84 h60
  text ".plot_File_Name" at 5440.5,-1064.84 h60
  text "PLOT NAME =" at 6246,-1064.84 h60
M9 Title Sheet:
  drawing of 57 lines, arcs and shapes, not listed
  text "1" at 739.84,8036.5 h70
  text "2" at 3235.5,8036.5 h70
  text "3" at 5724.84,8036.5 h70
  text "4" at 8231.51,8036.5 h70
  text "5" at 10730.5,8036.5 h70
  text "6" at 13235.5,8036.5 h70
  text "A" at -416.5,6893.5 h70
  text "A" at 14383.5,6893.5 h70
  text "B" at -416.5,4513.5 h70
  text "B" at 14383.5,4513.5 h70
  text "C" at -416.5,2138.5 h70
  text "C" at 14383.5,2138.5 h70
  text "PROJECT TITLE:" at 11343.5,277.5 h45
  text ".PRJ_Title" at 11393.5,144.17 h70
  text "DESIGNED FOR:" at 11343.5,-23.5 h45
  text ".PRJ_Customer" at 11393.5,-163.5 h70
  text "D" at -416.5,-231.5 h70
  text "D" at 14383.5,-231.5 h70
  text "FILE NAME:" at 11343.5,-323.5 h45
  text ".PCB_File_Name_No_Path" at 11393.5,-443.5 h70
  text "Texas Instruments (TI) and/or its licensors do not warrant the accuracy or completeness of this specification" at 6374,-605.34 h45
  text "ENGINEER:" at 11343.5,-613.5 h45
  text "LAYOUT BY:" at 12848.5,-613.5 h45
  text "or any information contained therein. TI and/or its licensors do not warrant that this design will meet" at 6329.01,-718 h45
  text ".PRJ_Engineer" at 11393.5,-768.49 h70
  text ".PCB_Layout" at 12899,-768.49 h70
  text "the specifications, will be suitable for your application or fit for any particular purpose, or will operate in" at 6329.01,-830.67 h45
  text ".Layer_Name" at 577,-858.49 h60
  text "ALTIUM DESIGNER VERSION:" at 12848.5,-923.5 h45
  text "an implementation. TI and/or its licensors do not warrant that the design is production worthy. You should" at 6329.01,-943.33 h45
  text "completely validate and test your design implementation to confirm the system functionality for your application." at 6374,-1056 h45
  text ".print_Scale" at 11393.5,-1056.83 h70
  text ".Application_BuildNumber" at 12899,-1056.83 h70
  text "1" at 739.84,-1263.5 h70
  text "2" at 3235.5,-1263.5 h70
  text "3" at 5724.84,-1263.5 h70
  text "4" at 8231.51,-1263.5 h70
  text "5" at 10730.5,-1263.5 h70
  text "6" at 13235.5,-1263.5 h70
M10 Fab Notes:
  drawing of 189 lines, arcs and shapes, not listed
  text "DESIGN INFORMATION" at 12382.02,6356.17 h60
  text "MIN. TRACK WIDTH:" at 11737.46,6224.05 h60
  text "8" at 12833.7,6224.05 h60
  text "MIL" at 12988.46,6224.05 h60
  text "MIN. CLEARANCE:" at 11737.46,6099.92 h60
  text "0.2" at 12773.7,6099.93 h60
  text "mm" at 12988.46,6099.92 h60
  text "MIN. VIA PAD SIZE:" at 11737.46,5975.8 h60
  text "10" at 12803.71,5975.8 h60
  text "MIL" at 12988.46,5975.8 h60
  text "0.05mm (2MIL)" at 12432.46,5845.9 h60
  text "MINIMUM ANNULAR RING" at 11408.23,5837.67 h60
  text "EXTERNAL" at 13140.46,5837.67 h60
  text "PER" at 11608.23,5727.55 h60
  text "IPC-D-275 CLASS 2 LEVEL C" at 11828.23,5727.54 h60
  text "MIL, HOLES" at 13316.46,5627.07 h60
  text "+/-" at 12924,5618.48 h60
  text "+/-" at 13778,5618.48 h60
  text "REGISTRATION TOLERANCES:" at 11408.23,5617.42 h60
  text "METAL" at 12608,5617.42 h60
  text "5" at 13184.2,5617.42 h60
  text "3" at 14017.2,5617.42 h60
  text "MIL" at 14133.46,5617.42 h60
  text "HOLE SIZE TOLERANCE (UNLESS OTHERWISE SPECIFIED):" at 11408.23,5519.1 h60
  text "+/-" at 13778,5516.23 h60
  text "3" at 14017.2,5515.17 h60
  text "MIL" at 14133.46,5515.17 h60
  text "MATERIAL:" at 11333.46,5377.52 h60
  text "FR-4 High Tg" at 12319.9,5249 h60
  text "X" at 12175.46,5241.01 h60
  text "FR-408" at 11754.46,5236.49 h60
  text "OTHER" at 13242.46,5236.49 h60
  text "48 MIL (1.2mm) +/-10%" at 12074.56,5093.46 h60
  text "X" at 11954.46,5091.01 h60
  text "THICKNESS:" at 11408.23,5085.24 h60
  text "OTHER" at 13359.46,5085.24 h60
  text "TOLERANCE:" at 11408.23,4946.92 h60
  text "X" at 12256.46,4946.92 h60
  text "ANSI IPC-6012 TYPE 3 CLASS 2" at 12434.48,4946.92 h60
  text "OTHER +/-" at 12434.46,4802.73 h60
  text "BOW & TWIST:" at 11408.23,4657.54 h60
  text "X" at 12256.46,4657.54 h60
  text "ANSI IPC-6012 TYPE 3 CLASS 2" at 12434.48,4657.54 h60
  text "OTHER +/-" at 12434.46,4510.85 h60
  text "DRILLING:" at 11333.46,4380.23 h60
  text "NC_DRILL FILES" at 13094.46,4275.04 h60
  text "REFERENCE:" at 11408.23,4271.1 h60
  text "X" at 12065.46,4271.01 h60
  text "AS SHOWN" at 12243.46,4271.1 h60
  text "X" at 12966.46,4271.1 h60
  text "OTHER" at 13392.46,4128.85 h60
  text "PTH COPPER THICKNESS:" at 11407.91,4125.32 h60
  text "X" at 12547.14,4125.32 h60
  text "20-30 um" at 12675.14,4125.32 h60
  text "BOARD FINISH:" at 11333.46,3977.73 h60
  text "SILKSCREEN:" at 11488.68,3867.6 h60
  text "X" at 12446.46,3867.6 h60
  text "TOP" at 12563.46,3867.6 h60
  text "X" at 12956.46,3867.6 h60
  text "BOTTOM" at 13074.46,3867.6 h60
  text "SILKSCREEN COLOR:" at 11488.68,3712.41 h60
  text "X" at 12445.46,3712.41 h60
  text "WHITE" at 12563.46,3712.41 h60
  text "OTHER" at 13074.46,3712.41 h60
  text "X" at 12576.46,3568.96 h60
  text "GREEN" at 12694.46,3568.96 h60
  text "OTHER" at 13312.46,3568.96 h60
  text "SOLDER RESIST COLOR:" at 11488.68,3562.1 h60
  text "X" at 12576.46,3414.71 h60
  text "MATTE" at 12694.46,3414.71 h60
  text "SEMI-GLOSS" at 13312,3414.07 h60
  text "IMMERSION GOLD (ENIG)" at 12394.46,3241.94 h60
  text "ENEPIG" at 13732,3234.72 h60
  text "SURFACE FINISH:" at 11333.46,3233.72 h60
  text "X" at 12216.46,3233.72 h60
  text "IMM. TIN/SILVER OR EQUIV" at 11663,3096.4 h60
  text "OTHER" at 13094.46,3092.47 h60
  text "ARRAY/PANEL:" at 11333.46,2937.09 h60
  text "CUT AND TRIM PER M1 BOARD OUTLINE" at 12394.46,2928.87 h60
  text "N.C. ROUTE" at 12394.46,2792.9 h60
  text "X" at 13082.46,2792.9 h60
  text "V. SCORE" at 13260.46,2792.9 h60
  text "CERTIFICATION:" at 11333.46,2663.77 h60
  text "MATERIALS AND WORKMANSHIP FOR ALL PCBS" at 12058.46,2663.77 h60
  text "TO MEET OR EXCEED THE REQUIREMENTS OF:" at 12058.46,2569.71 h60
  text "X" at 11695.97,2441.08 h60
  text "ANSI IPC-A-600F CLASS ->" at 11823.96,2441.08 h60
  text "X" at 13471.97,2441.08 h60
  text "2" at 13581.96,2441.08 h60
  text "1" at 13266.96,2439.58 h60
  text "3" at 13935.96,2439.58 h60
  text "X" at 12507.97,2293.39 h60
  text "RoHS" at 12635.96,2293.39 h60
  text "OTHER" at 13280.36,2293.39 h60
  text "PER ORDER" at 13677.42,2293.39 h60
  text "ALL BOARDS MUST MEET OR EXCEED UL94-V0 REQUIREMENTS." at 11361,2139.57 h60
  text "PCB MUST BEAR THE UL94V-0 UL REGISTERED MATERIAL ID NUMBER" at 11361,2023.5 h60
  text "ADDITIONAL REQUIREMENTS:" at 11333.46,1854.08 h60
  text "MICROSECTION:" at 11408.23,1746.95 h60
  text "YES" at 12313.96,1746.95 h60
  text "REQUIRED" at 13175.46,1602.62 h60
  text "BARE BOARD ELEC. TEST:" at 11408.23,1599.76 h60
  text "NONE" at 12713.96,1599.76 h60
  text "X" at 13057.46,1599.76 h60
  text "PER ORDER" at 13767.46,1599.76 h60
  text "XX MIL VIAS REQUIRE NON-CONDUCTIVE FILL AND PLANARIZE" at 11576.38,1394.82 h59
  text "XX MIL VIAS REQUIRE CONDUCTIVE FILL AND PLANARIZE" at 11584.38,1290.84 h60
  text "OUTER XX MIL TRACES REQUIRE 50 OHM SINGLE-ENDED IMPEDANCE" at 11583.39,1127.46 h58
  text "LAYER 2 & 3 (INNER LAYERS) XX MIL WIDE, XX MIL SPACE / TRACES REQUIRE 100 OHM DIFFERENTIAL IMPEDANCE" at 11575.39,891.74 h60
  text ".Layer_Name" at 577,-858.49 h60
M11 Gerber Information:
  lines w10: -292,-930.17 6308,-930.17 ; -292,-726.83 6310,-726.83 ; -292,-523.5 -292,-1133.5 3713,-1133.5 6310,-1133.5 6310,-523.5 -291.5,-523.5 -291.5,-1133.5 1284,-1133.5 ; 2173,-1133.5 2173,-523.5 ; 3440,-726.83 3440,-523.5 ; 4280,-726.83 4280,-523.5 ; 4902,-1140 4902,-937.17
  text "ALL ARTWORK VIEWED FROM TOP SIDE" at -228.5,-655.67 h60
  text "BOARD #:" at 2248,-655.67 h60
  text ".PRJ_Number" at 2793.5,-655.67 h60
  text "REV:" at 3638,-655.67 h60
  text ".PCB_Rev" at 3929.5,-655.67 h60
  text "SVN REV:" at 4476,-655.67 h60
  text ".VersionControl_RevNumber" at 4982,-655.67 h60
  text "LAYER NAME =" at -228.5,-858.49 h60
  text "TID #:" at 2248,-859 h60
  text ".TID" at 2793.5,-859 h60
  text "PLOT NAME =" at -228.5,-1064.34 h60
  text ".plot_File_Name" at 577,-1064.34 h60
  text "GENERATED    :" at 2250,-1064.34 h60
  text ".Print_Date" at 3119.5,-1064.34 h60
  text ".Print_Time" at 3848.5,-1064.34 h60
  text "TEXAS INSTRUMENTS" at 5113,-1064.34 h60
M12 Stackup:
  text ".Layer_Name" at 577,-858.49 h60
M13 Component Bodies Top:
  text ".Layer_Name" at 577,-858.49 h60
M14 Component Bodies Bottom:
  text ".Layer_Name" at 577,-858.49 h60
M15 Courtyards Top:
  text ".Layer_Name" at 577,-858.49 h60
M16 Courtyards Bottom:
  text ".Layer_Name" at 577,-858.49 h60
Drill Drawing:
  circle w10: c5407.67,4525.17 r16.13
  lines w10: 5391.54,4291.32 5423.8,4291.32 5423.8,4323.57 5391.54,4323.57 5391.54,4291.32 ; 5391.54,4363.89 5407.67,4371.96 5423.8,4363.89 5415.73,4380.02 5423.8,4396.15 5407.67,4388.08 5391.54,4396.15 5399.61,4380.02 5391.54,4363.89 ; 5391.54,4444.53 5399.61,4444.53 5399.61,4436.47 5415.73,4436.47 5415.73,4444.53 5423.8,4444.53 5423.8,4460.66 5415.73,4460.66 5415.73,4468.72 5399.61,4468.72 5399.61,4460.66 5391.54,4460.66 5391.54,4444.53 ; 5391.54,4613.88 5423.8,4613.88 5407.67,4581.62 5391.54,4613.88
  lines w12: 5361,4269.54 7245.11,4269.54 ; 5361,4632.42 7245.11,4632.42 ; 5557.97,4196.97 5557.97,4705 ; 5751.47,4196.97 5751.47,4705 ; 6122.41,4196.97 6122.41,4705 ; 6273.47,4196.97 6273.47,4705 ; 6492.12,4196.97 6492.12,4705 ; 6914.98,4196.97 6914.98,4705 ; 5361,4196.97 7245.11,4196.97 7245.11,4705 5361,4705 5361,4196.97
  text "Symbol" at 5404.55,4654.2 h42
  text "Quantity" at 5579.74,4654.2 h42
  text "Finished Hole Size" at 5773.25,4654.2 h42
  text "Plated" at 6144.19,4654.2 h42
  text "Hole Type" at 6295.25,4654.2 h42
  text "Drill Layer Pair" at 6513.9,4654.2 h42
  text "Hole Tolerance" at 6936.75,4654.2 h42
  text "10" at 5579.74,4581.62 h35
  text "7.87mil (0.200mm)" at 5773.25,4581.62 h35
  text "PTH" at 6144.19,4581.62 h35
  text "Round" at 6295.25,4581.62 h35
  text "Top Layer - Bottom Layer" at 6513.9,4581.62 h35
  text "3" at 5579.74,4509.04 h35
  text "10.00mil (0.254mm)" at 5773.25,4509.04 h35
  text "PTH" at 6144.19,4509.04 h35
  text "Round" at 6295.25,4509.04 h35
  text "Top Layer - Bottom Layer" at 6513.9,4509.04 h35
  text "6" at 5579.74,4436.47 h35
  text "15.00mil (0.381mm)" at 5773.25,4436.47 h35
  text "PTH" at 6144.19,4436.47 h35
  text "Round" at 6295.25,4436.47 h35
  text "Top Layer - Bottom Layer" at 6513.9,4436.47 h35
  text "7" at 5579.74,4363.89 h35
  text "20.00mil (0.508mm)" at 5773.25,4363.89 h35
  text "PTH" at 6144.19,4363.89 h35
  text "Round" at 6295.25,4363.89 h35
  text "Top Layer - Bottom Layer" at 6513.9,4363.89 h35
  text "13" at 5579.74,4291.32 h35
  text "40.00mil (1.016mm)" at 5773.25,4291.32 h35
  text "PTH" at 6144.19,4291.32 h35
  text "Round" at 6295.25,4291.32 h35
  text "Top Layer - Bottom Layer" at 6513.9,4291.32 h35
  text "39 Total" at 5579.74,4218.74 h35
  text ".Layer_Name" at 577,-858.49 h60
M17 Embedded Cavity:
  text ".Layer_Name" at 577,-858.49 h60
M18 Embedded Assembly:
  text ".Layer_Name" at 577,-858.49 h60
M19 Embedded Keepout:
  text ".Layer_Name" at 577,-858.49 h60

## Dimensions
0,-400 to 1000,-400 on M2 Board Dimensions
0,0 to 0,1200 on M2 Board Dimensions
0,0 to 2300,0 on M2 Board Dimensions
